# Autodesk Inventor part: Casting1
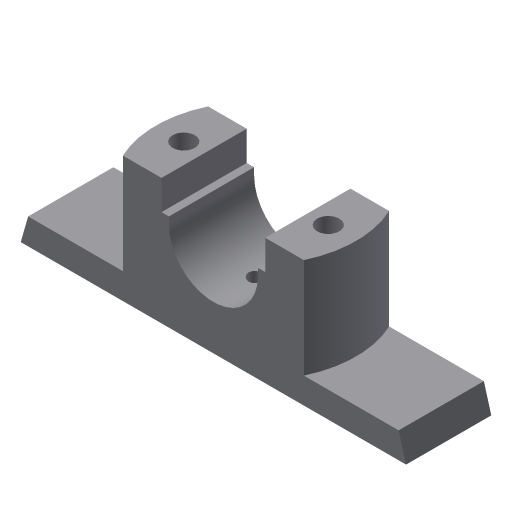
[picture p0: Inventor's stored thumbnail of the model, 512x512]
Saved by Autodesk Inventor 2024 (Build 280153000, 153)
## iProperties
Created: 2009-04
Part Number: Casting1
Document SubType Name: Modeling
Designer: Sham
Density: 1 g/cm^3
Material: Generic
Appearance: Default
Author: Sham
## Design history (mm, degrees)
sketch "Sketch1"
  geometry: L1 (-104, 0)-(104, 0); L2 (-104, 0)-(-100, 14); L3 (-100, 14)-(100, 14); L4 (100, 14)-(104, 0); 1 further point
  constraints: 8 end point, 1 horizontal, 1 midpoint, 1 parallel, 1 other
  dimensions: "d0" = 208 distance of L1.start L1.end; "d1" = 104 distance of L1.end point (0, 0); "d2" = 4 horizontal distance of L1.start L2.end; "d3" = 4 horizontal distance of L1.end L3.end; "d10" = 14 distance between parallel lines of L1 L3
extrude "Extrusion1" new body sketch "Sketch1" stored distance "d4" = 46; taper "d5" = 0 deg
sketch "Sketch2"
  geometry: L1 (51.143, 46)-(148.857, 46); L2 (148.857, 0)-(51.143, 0); A1 r 54 centre (100, 23) between (51.143, 46) and (51.143, 0); A2 r 54 centre (100, 23) between (148.857, 0) and (148.857, 46)
  constraints: 4 end point, 4 point on circle, 2 centre point, 1 parallel
extrude "Extrusion2" join sketch "Sketch2" distance "d8" = 54; taper "d9" = 0 deg
sketch "Sketch3"
  geometry: L1 (-28, 68)-(-28, 52); L2 (-28, 52)-(-24, 52); L3 (28, 68)-(28, 52); L4 (28, 52)-(24, 52); L5 (-28, 68)-(28, 68); L6 (-100, 14)-(-48.857, 14) reference; L7 (0, 48)-(0, 19); L8 (48.857, 14)-(100, 14) reference; L9 (48.857, 68)-(-48.857, 68) reference; L10 (-24, 48)-(-24, 52); L11 (24, 48)-(24, 52); A1 r 24 centre (0, 48) between (-24, 48) and (24, 48); 1 further point
  constraints: 16 end point, 5 perpendicular, 2 point on circle, 2 symmetric about line, 1 centre point, 1 tangent, 1 vertical alignment, 1 other
  dimensions: "d11" = 16 distance of L1.start L1.end; "d16" = 24 radius of A1; "d17" = 16 distance of L3.start L3.end; "d52" = 56 distance between parallel lines of L1 L3; "d54" = 54 distance between parallel lines of L8 L9 (derived)
extrude "Extrusion3" cut sketch "Sketch3" distance "d18" = 54; taper "d19" = 0 deg
sketch "Sketch5"
  geometry: L1 (208, 0)-(0, 0) reference; L2 (52, -10)-(78, -10); L3 (78, -10)-(78, -36); L4 (78, -36)-(52, -36); L5 (52, -36)-(52, -10); L6 (130, -10)-(156, -10); L7 (156, -10)-(156, -36); L8 (156, -36)-(130, -36); L9 (130, -36)-(130, -10); L10 (0, -46)-(208, -46) reference; L11 (104, -23)-(104, -46)
  constraints: 18 end point, 5 perpendicular, 4 parallel, 2 horizontal, 1 midpoint
  dimensions: "d30" = 26 distance of L2.start L2.end; "d31" = 10 distance between parallel lines of L2 L1; "d32" = 10 distance between parallel lines of L1 L6; "d65" = 26 distance between parallel lines of L3 L11; "d66" = 26 distance between parallel lines of L9 L11
extrude "Extrusion5" cut sketch "Sketch5" distance "d34" = 10; taper "d35" = 0 deg
sketch "Sketch6"
  geometry: L1 (148.857, 0)-(128, 0) reference; L2 (72, 0)-(51.143, 0) reference; L3 (0, 46)-(0, 0) reference; L4 (200, 46)-(200, 0) reference; C1 r 6 at (61, 23); C2 r 6 at (139, 23); 1 further point
  constraints: 2 centre point, 1 equal radius
  dimensions: "d36" = 12 diameter of C1; "d37" = 78 distance of C2.centre C1.centre; "d39" = 39 distance of C2.centre point (100, 23); "d58" = 39 distance of C1.centre point (100, 23); "d59" = 23 distance from line of L1 C2.centre; "d60" = 23 distance from line of L2 C1.centre; "d61" = 61 distance from line of L3 C1.centre; "d62" = 61 distance from line of L4 C2.centre (derived)
extrude "Extrusion6" cut sketch "Sketch6" extent not by distance; stored distance "d40" = 10; taper "d41" = 0 deg
workplane "Work Plane1"
sketch "Sketch7"
  geometry: L1 (-4, 46)-(204, 46) reference; L2 (-4, 0)-(-4, 46) reference; 1 further point
  dimensions: "d43" = 23 distance from line of L1 point (100, 23); "d44" = 104 distance from line of point (100, 23) L2
hole "Hole1" sketch "Sketch7" diameter "d45" = 8; stored, may be unused: countersink angle "d49" = 90 deg, drill point angle "d51" = 118 deg; dims "d46" = 6, "d47" = 8, "d48" = 16, "d50" = 8
body "Solid1"
other parameters: "d6" = 108, "d42" = -52
